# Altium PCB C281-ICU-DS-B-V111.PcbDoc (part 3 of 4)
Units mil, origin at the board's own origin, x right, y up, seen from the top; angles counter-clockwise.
Board outline 9370.03 x 5995.03 mil, 2 copper layers (Top Layer, Bottom Layer); 468 components, 321 nets, 1241 pads, 808 vias.
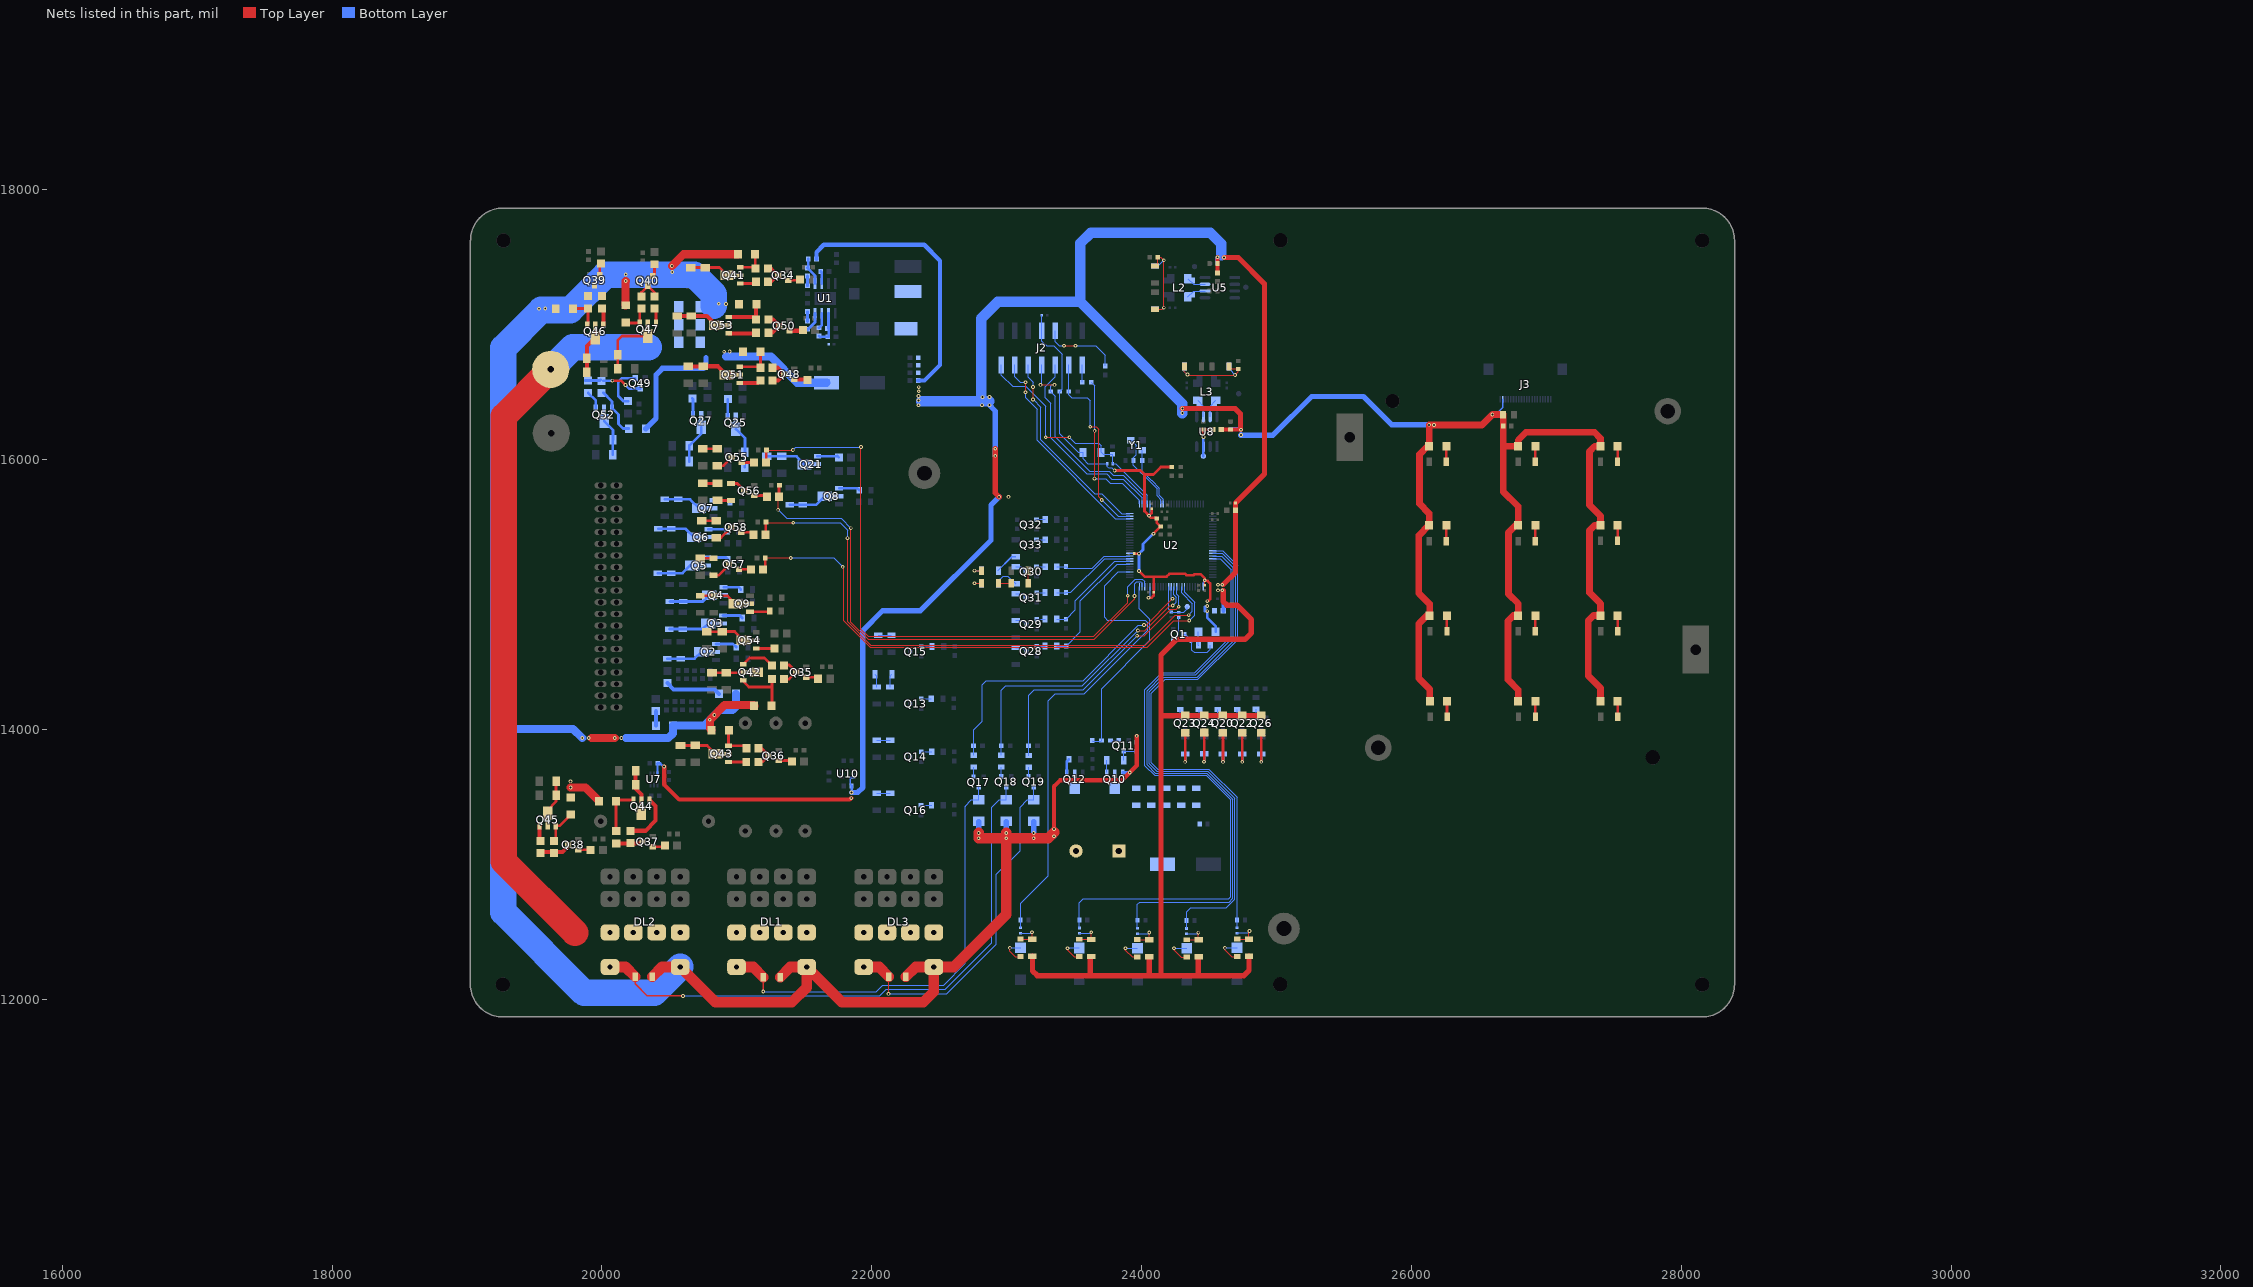
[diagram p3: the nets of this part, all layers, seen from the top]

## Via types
v1: diameter 27.56, hole 13.78, Top Layer to Bottom Layer, tented both sides, 808 vias

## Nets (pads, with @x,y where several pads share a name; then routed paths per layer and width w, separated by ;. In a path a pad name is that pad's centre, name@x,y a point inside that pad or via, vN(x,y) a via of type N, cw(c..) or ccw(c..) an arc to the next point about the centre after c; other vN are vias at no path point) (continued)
NetC35_1: C35.1 FB5.1 TP18.1 U8.3 | length 262.3
  Top Layer w7.87: v1@24457.48,16169.87 v1(24457.95,16169.4)
  Top Layer w19.68: v1@24457.48,16169.87 C35.1@24457.48,16223.93 FB5.1@24521.48,16223.93
  Bottom Layer w19.68: TP18.1@24457.48,16027 24457.48,16037.93 24457.95,16037.46 U8.3@24457.95,16097.48 v1(24457.95,16169.4)
NetC36_1: C36.1 R43.1 R44.1 R126.1 R128.1 | length 701.2
  Top Layer w7.87: R126.1@24100.09,17114.69 24152.11,17114.69 v1(24165.09,17127.68) v1(24165.09,17478.68) 24143.09,17500.68 C36.1@24119.09,17500.68 24119.09,17455.66 R44.1@24100.09,17436.66
  Bottom Layer w7.87: R128.1@24100.09,17114.69 24152.11,17114.69 v1(24165.09,17127.68) ; R43.1@24100.09,17436.66 24123.08,17436.66 v1(24165.09,17478.68)
NetC38_1: C38.1 R125.1 R127.1 R129.1 R130.1 | length 699.7
  Top Layer w7.87: R129.1@24317.6,16689.76 24317.6,16653.81 v1(24339.48,16631.93) 24343.48,16627.93 v1(24693.48,16627.93) 24716.48,16650.93 C38.1@24716.48,16672.93 24665.14,16672.93 R127.1@24648.31,16689.76
  Bottom Layer w7.87: R130.1@24317.6,16689.76 24317.6,16653.81 v1(24339.48,16631.93) ; R125.1@24648.31,16689.76 24648.31,16673.1 v1(24693.48,16627.93)
NetC52_2: C52.2 U1.6 | length 93
  Bottom Layer w20: C52.2@21622.08,17396.11 21629.39,17388.79 U1.6@21629.39,17306.11
NetC53_1: C53.1 C54.1 R135.2 R136.2 R137.2 R138.2 R140.2 SP1.1
NetD4_2: D4.2 Q41.E R211.1 | length 221.9
  Top Layer w20: Q41.E@21024.33,17426.53 21129.75,17426.53 R211.1@21135.13,17421.16 ; D4.2@21135.13,17524 R211.1@21135.13,17421.16 ; R211.1@21139.36,17416.92 R211.1@21135.13,17421.16
NetD6_1: D6.1 SW1.2 | length 211.4
  Top Layer w7.87: v1(23450,12379) 23450,12367.04 23500.21,12316.83 D6.1@23538.83,12316.83
  Bottom Layer w7.87: v1(23450,12379) 23452.3,12381.3 SW1.2@23538.83,12381.3
NetD6_2: D6.2 R45.1 R46.1 | length 239.6
  Top Layer w7.87: D6.2@23538.83,12445.77 23625.93,12445.77 23626.93,12444.77 v1@23626.93,12490.11 ; v1(23626.93,12498) v1@23626.93,12490.11 ; v1@23627.43,12489.62 v1@23626.93,12490.11
  Bottom Layer w7.87: R46.1@23538.83,12489.57 23627.38,12489.57 23626.93,12490.02 v1(23626.93,12498)
NetD7_2: D7.2 Q42.E R212.1 | length 442.5
  Top Layer w20: Q42.E@21047.84,14365 21047.84,14357.16 21089,14316 21252.86,14316 21259.86,14309 ; D7.2@21255.68,14175 21259.86,14179.18 21259.86,14309 ; R212.1@21259.86,14376 21259.86,14309
NetD8_1: D8.1 SW5.2 | length 214.7
  Top Layer w7.87: v1(24617,12382) 24617,12369.58 24668.75,12317.83 D8.1@24707.37,12317.83
  Bottom Layer w7.87: v1(24617,12382) 24617.3,12382.3 SW5.2@24707.37,12382.3
NetD8_2: D8.2 R55.1 R58.1 | length 254.5
  Top Layer w7.87: D8.2@24707.37,12446.77 24794.48,12446.77 R55.1@24795,12446.25 ; R55.1@24795.95,12445.29 24795.95,12503.21 v1(24799,12506.25)
  Bottom Layer w7.87: R58.1@24707.37,12490.57 24712.29,12495.49 24799,12495.49 v1(24799,12506.25)
NetD9_1: D9.1 SW2.2 | length 198.4
  Top Layer w7.87: v1(23023.55,12382.3) 23023.55,12357.95 23063.67,12317.83 D9.1@23102.29,12317.83
  Bottom Layer w7.87: v1(23023.55,12382.3) SW2.2@23102.29,12382.3
NetD9_2: D9.2 R119.1 R120.1 | length 243.1
  Top Layer w7.87: D9.2@23102.29,12446.77 R119.1@23189.4,12446.77 ; v1(23187.63,12498) v1@23187.63,12493.88 ; R119.1@23190.87,12445.29 R119.1@23189.4,12446.77 ; v1@23190.89,12490.62 v1@23187.63,12493.88 ; v1@23187.63,12493.88 23187.63,12448.54 R119.1@23189.4,12446.77
  Bottom Layer w7.87: R120.1@23102.29,12490.57 23190.84,12490.57 23187.63,12493.78 v1(23187.63,12498)
NetD10_2: D10.2 Q43.E R213.1 | length 257.6
  Top Layer w20: D10.2@20939.93,13996 20937.42,13993.5 Q43.E@20937.42,13879.67 21052.17,13879.67 R213.1@21070.17,13861.67
NetD11_2: D11.2 Q44.E R214.1 | length 356.4
  Top Layer w20: R214.1@20106,13247 20104.06,13248.94 D11.2@20104.06,13470 20112.39,13478.33 Q44.E@20233.25,13478.33
NetD12_1: D12.1 SW3.2 | length 213
  Top Layer w7.87: v1(23880,12379) 23880,12365.4 23930.56,12314.83 D12.1@23969.18,12314.83
  Bottom Layer w7.87: v1(23880,12379) 23880.3,12379.3 SW3.2@23969.18,12379.3
NetD12_2: D12.2 R65.1 R66.1 | length 241.1
  Top Layer w7.87: D12.2@23969.18,12443.77 R65.1@24056.29,12443.77 ; v1(24056.29,12495.98) v1@24056.29,12489.11 ; R65.1@24057.76,12442.29 R65.1@24056.29,12443.77 ; v1@24057.78,12487.62 v1@24056.29,12489.11 ; R65.1@24056.29,12443.77 v1@24056.29,12489.11
  Bottom Layer w7.87: R66.1@23969.18,12487.57 24057.73,12487.57 24056.29,12489.01 v1(24056.29,12495.98)
NetD13_2: D13.2 Q45.E R215.1 | length 263.4
  Top Layer w20: R215.1@19644.01,13175.19 19657.76,13188.94 Q45.E@19657.76,13283.86 19657.76,13287.86 19687.43,13287.86 D13.2@19769,13369.44
NetD14_1: D14.1 SW4.2 | length 220.1
  Top Layer w7.87: v1(24240,12379) 24240,12368.57 24294.74,12313.83 D14.1@24333.35,12313.83
  Bottom Layer w7.87: v1(24240,12379) 24240.7,12378.3 SW4.2@24333.35,12378.3
NetD14_2: D14.2 R71.1 R72.1 | length 239
  Top Layer w7.87: D14.2@24333.35,12442.77 24420.46,12442.77 v1@24420.46,12488.11 ; v1(24420.46,12495) v1@24420.46,12488.11 ; v1@24421.95,12486.62 v1@24420.46,12488.11
  Bottom Layer w7.87: R72.1@24333.35,12486.57 24421.91,12486.57 24420.46,12488.01 v1(24420.46,12495)
NetD15_2: D15.2 Q46.E R216.1 | length 237.9
  Top Layer w20: D15.2@19784.68,17121 19895.5,17121 R216.1@19896.99,17122.5 19896.99,17007.07 Q46.E@19890.25,17000.33
NetD19_2: D19.2 Q47.E R217.1 | length 218.5
  Top Layer w20: D19.2@20174.55,17018 20178.77,17013.78 Q47.E@20280.25,17013.78 20280.25,17108.25 R217.1@20292,17120
NetD20_2: D20.2 Q51.E R233.1 | length 278.5
  Top Layer w20: Q51.E@21020.53,16689.25 21168.06,16689.25 R233.1@21175.3,16682.01 21175.3,16800.26 D20.2@21173.56,16802
NetD21_2: D21.2 Q52.E R234.1 | length 367.9
  Bottom Layer w20: R234.1@20010,16496.59 20074.75,16431.84 Q52.E@20074.75,16383.33 20122,16336.08 20122,16266 20157,16231 D21.2@20198.44,16231
NetD22_2: D22.2 Q53.E R235.1 | length 322
  Top Layer w30: Q53.E@20939.93,17057.35 21125.98,17057.35 R235.1@21142.73,17040.6 21142.73,17150 D22.2@21144.74,17152
NetD24_1: D24.1 R240.2 | length 106
  Bottom Layer w30: D24.1@20399,14030 R240.2@20399,14136.04
NetD25_1: D25.1 R244.2 | length 414.7
  Bottom Layer w30: R244.2@20484.5,14344.61 20531.11,14298 20832.56,14298 D25.1@20866,14264.56
NetJ2_1: J2.1 R10.2 | length 128.4
  Bottom Layer w7.87: R10.2@23560,16575 J2.1@23560,16703.43
NetJ2_6: J2.6 R11.1 | length 573
  Top Layer w7.87: v1(23425,16845) v1(23510,16845)
  Bottom Layer w7.87: J2.6@23360,16956.57 23360,16875 23390,16845 v1(23425,16845) ; v1(23510,16845) 23660,16845 23730,16775 R11.1@23730,16695
NetL2_2: L2.2 U5.6 | length 144.4
  Bottom Layer w7.87: L2.2@24343.09,17208.75 24385.02,17250.68 U5.6@24470.09,17250.68
NetL2_3: L2.3 U5.7 | length 144.4
  Bottom Layer w7.87: L2.3@24343.08,17342.6 24385.01,17300.68 U5.7@24470.09,17300.68
NetL3_2: L3.2 U8.6 | length 139.6
  Bottom Layer w7.87: L3.2@24416.03,16439.76 24457.95,16397.84 U8.6@24457.95,16317.48
NetL3_3: L3.3 U8.7 | length 139.7
  Bottom Layer w7.87: U8.7@24507.95,16317.48 24507.95,16397.84 L3.3@24549.88,16439.77
NetLED1_2: LED1.2 R22.2 | length 100.1
  Bottom Layer w7.87: LED1.2@24421.44,14725 24421.44,14625.26 R22.2@24421.69,14625
NetLED4_2: LED4.2 R76.1 | length 274.9
  Top Layer w19.68: v1(24322.73,13760.56) LED4.2@24322.73,13976.47
  Bottom Layer w19.68: v1(24322.73,13760.56) R76.1@24322.73,13819.56
NetLED5_2: LED5.2 R77.1 | length 274.9
  Top Layer w19.68: v1(24463.2,13761.27) LED5.2@24463.2,13977.17
  Bottom Layer w19.68: v1(24463.2,13761.27) R77.1@24463.2,13820.26
NetLED6_2: LED6.2 R78.1 | length 274.9
  Top Layer w19.68: v1(24603.04,13760.56) LED6.2@24603.05,13976.47
  Bottom Layer w19.68: v1(24603.04,13760.56) R78.1@24603.04,13819.56
NetLED7_2: LED7.2 R82.1 | length 115.2
  Top Layer w20: R82.1@26257.99,15985 26258.56,15985.57 LED7.2@26258.56,16100
NetLED8_2: LED8.2 R83.1 | length 115.2
  Top Layer w20: R83.1@26917.99,15985 26918.56,15985.57 LED8.2@26918.56,16100
NetLED9_2: LED9.2 R79.1 | length 274.9
  Top Layer w19.68: v1(24745.84,13760.56) LED9.2@24745.84,13976.47
  Bottom Layer w19.68: v1(24745.84,13760.56) R79.1@24745.84,13819.56
NetLED10_2: LED10.2 R85.1 | length 115.2
  Top Layer w20: R85.1@27527.99,15985 27528.56,15985.57 LED10.2@27528.56,16100
NetLED11_2: LED11.2 R80.1 | length 274.9
  Top Layer w19.68: v1(24886.43,13760.56) LED11.2@24886.43,13976.47
  Bottom Layer w19.68: v1(24886.43,13760.56) R80.1@24886.43,13819.56
NetLED12_2: LED12.2 R87.1 | length 120.2
  Top Layer w7.87: LED12.2@26257.99,15514.43 LED12.2@26258.56,15515
  Top Layer w19.68: R87.1@26257.99,15395 LED12.2@26257.99,15514.43
NetLED14_2: LED14.2 R89.1 | length 120.2
  Top Layer w20: R89.1@26917.99,15395 26918.56,15395.57 LED14.2@26918.56,15515
NetLED16_2: LED16.2 R91.1 | length 115.2
  Top Layer w20: R91.1@27527.99,15400 27528.56,15400.57 LED16.2@27528.56,15515
NetLED18_2: LED18.2 R93.1 | length 115.4
  Top Layer w20: LED18.2@26262.13,14845 26262.13,14730.87 R93.1@26262.99,14730
NetLED20_2: LED20.2 R95.1 | length 115.2
  Top Layer w20: R95.1@26917.99,14730 26918.56,14730.57 LED20.2@26918.56,14845
NetLED22_2: LED22.2 R97.1 | length 115.6
  Top Layer w20: LED22.2@27528.56,14845 27530,14843.56 R97.1@27530,14730
NetLED23_2: LED23.2 R98.1 | length 115.6
  Top Layer w20: LED23.2@26263.56,14210 26263.56,14096.44 R98.1@26265,14095
NetLED24_2: LED24.2 R99.1 | length 115.6
  Top Layer w20: LED24.2@26918.56,14210 26918.56,14096.44 R99.1@26920,14095
NetLED25_2: LED25.2 R100.1 | length 115.6
  Top Layer w20: LED25.2@27528.56,14210 27528.56,14096.44 R100.1@27530,14095
NetQ1_B: Q1.B R24.1 | length 177.4
  Bottom Layer w7.87: Q1.B@24234.63,14670.6 24275,14710.97 R24.1@24275,14831.31
NetQ1_C: Q1.C R22.1 TP13.1 | length 331.2
  Bottom Layer w7.87: Q1.C@24313.37,14708 24323,14708 24373,14658 24373,14588.91 24389.54,14572.36 24486.09,14572.36 24508.31,14594.58 R22.1@24508.31,14625
NetQ2_B: Q2.B R103.1 | length 161.6
  Bottom Layer w20: Q2.B@20844.53,14634.54 20971.57,14634.54 R103.1@20996.01,14610.11
NetQ2_C: Q2.C R26.1 R27.1 | length 271.9
  Bottom Layer w20: R27.1@20485.25,14525.42 R26.1@20583.67,14525.42 20686.29,14525.42 Q2.C@20736.4,14575.53
NetQ3_B: Q3.B R106.1 | length 150.9
  Bottom Layer w20: Q3.B@20896.45,14845.44 21022.3,14845.44 R106.1@21040.01,14827.73
NetQ3_C: Q3.C R28.1 R29.1 | length 305.4
  Bottom Layer w20: R28.1@20500.1,14744.82 R29.1@20598.53,14744.82 20746.71,14744.82 Q3.C@20788.31,14786.43
NetQ4_B: Q4.B R107.1 | length 133.5
  Bottom Layer w20: Q4.B@20902.53,15055.3 21011.98,15055.3 R107.1@21029.01,15038.28
NetQ4_C: Q4.C R30.1 R31.1 | length 309.9
  Bottom Layer w20: R31.1@20503.82,14949.67 R30.1@20602.25,14949.67 20747.78,14949.67 Q4.C@20794.4,14996.28
NetQ5_B: Q5.B R108.1 | length 160.5
  Bottom Layer w20: Q5.B@20778.2,15275.02 20917.62,15275.02 R108.1@20932.51,15260.12
NetQ5_C: Q5.C R32.1 R74.1 | length 278.6
  Bottom Layer w20: R32.1@20415.1,15159.01 R74.1@20513.53,15159.01 20596.7,15159.01 20653.7,15216 Q5.C@20670.06,15216
NetQ6_B: Q6.B R109.1 | length 144
  Bottom Layer w20: Q6.B@20790.04,15485.65 20911.81,15485.65 R109.1@20927.51,15469.94
NetQ6_C: Q6.C R88.1 R90.1 | length 290.9
  Bottom Layer w20: R88.1@20416.72,15488.65 R90.1@20515.15,15488.65 20619.88,15488.65 Q6.C@20681.9,15426.63
NetQ7_B: Q7.B R110.1 | length 129
  Bottom Layer w20: Q7.B@20826.89,15700.01 20933.66,15700.01 R110.1@20949.36,15684.31
NetQ7_C: Q7.C R92.1 R94.1 | length 280
  Bottom Layer w20: R92.1@20465.9,15706.5 R94.1@20564.32,15706.5 20653.25,15706.5 Q7.C@20718.75,15641
NetQ8_B: Q8.B R111.1 | length 154.2
  Bottom Layer w20: Q8.B@21758.57,15787.91 21893.33,15787.91 R111.1@21907.04,15774.2
NetQ8_C: Q8.C R96.1 R101.1 | length 284.4
  Bottom Layer w20: R101.1@21391.43,15667.58 R96.1@21489.85,15667.58 21589.11,15667.58 Q8.C@21650.43,15728.89
NetQ9_B: Q9.B R123.1 | length 147.8
  Top Layer w20: Q9.B@21098,14873 21236.95,14873 R123.1@21243.19,14879.23
NetQ9_C: Q9.C R121.1 R122.1 | length 287.4
  Top Layer w20: R121.1@20726.86,14990.98 R122.1@20827.2,14990.98 20930.89,14990.98 Q9.C@20989.86,14932.02
NetQ10_2: Q10.2 R135.1 R136.1 R137.1 R138.1 R140.1
NetQ10_3: Q10.3 R134.2 | length 88.6
  Bottom Layer w7.87: Q10.3@23741.95,13682.33 R134.2@23741.95,13770.91
NetQ11_B: Q11.B R139.2 | length 60.5
  Bottom Layer w7.87: R139.2@23770.13,13918.91 23770.49,13918.55 Q11.B@23830.53,13918.55
NetQ11_C: Q11.C R133.2 R134.1 | length 165
  Bottom Layer w7.87: R134.1@23867.93,13770.91 Q11.C@23867.93,13839.81 R133.2@23963.99,13839.81
NetQ12_2: Q12.2 SP1.2
NetQ12_3: Q12.3 R142.2 | length 104.2
  Bottom Layer w19.68: Q12.3@23445.37,13682.33 23445.37,13764.23 R142.2@23461.12,13779.98
NetQ13_B: Q13.B R59.2 | length 75.2
  Bottom Layer w7.87: Q13.B@22366.14,14228.74 R59.2@22441.35,14228.74
NetQ14_B: Q14.B R62.2 | length 77.2
  Bottom Layer w7.87: Q14.B@22366.14,13835.04 R62.2@22443.32,13835.04
NetQ15_B: Q15.B R73.2 | length 79.9
  Bottom Layer w7.87: Q15.B@22366.14,14615.75 R73.2@22446,14615.75
NetQ16_B: Q16.B R148.2 | length 79.3
  Bottom Layer w7.87: Q16.B@22363.78,13438.98 R148.2@22443.09,13438.98
NetQ17_B: Q17.B R150.2 | length 71.6
  Bottom Layer w7.87: Q17.B@22754.67,13650.58 R150.2@22754.67,13722.22
NetQ18_B: Q18.B R151.2 | length 71.1
  Bottom Layer w7.87: R151.2@22959.08,13722.22 22959.6,13721.7 Q18.B@22959.6,13651.37
NetQ19_B: Q19.B R152.2 | length 69.9
  Bottom Layer w7.87: Q19.B@23162.35,13651.37 R152.2@23162.35,13721.24
NetQ20_B: Q20.B R156.2 | length 62.1
  Bottom Layer w7.87: R156.2@24565.45,14148.62 24565.45,14086.8 Q20.B@24565.65,14086.6
NetQ21_B: Q21.B R35.1 | length 169.6
  Bottom Layer w16: R35.1@21742.14,16031.11 21747.14,16026.11 R35.1@21756.39,16016.86
  Bottom Layer w20: Q21.B@21597.71,16026.11 R35.1@21747.14,16026.11
NetQ21_C: Q21.C R7.1 R8.1 | length 304.6
  Bottom Layer w20: R7.1@21222.02,16025.91 21333.02,16025.91 R8.1@21334.02,16024.91 21441.34,16024.91 Q21.C@21501.39,15964.86
NetQ22_B: Q22.B R159.2 | length 62
  Bottom Layer w7.87: Q22.B@24708.44,14086.6 R159.2@24708.44,14148.62
NetQ23_B: Q23.B R160.2 | length 62
  Bottom Layer w7.87: Q23.B@24285.33,14086.6 R160.2@24285.33,14148.62
NetQ24_B: Q24.B R164.2 | length 62
  Bottom Layer w7.87: Q24.B@24425.8,14086.6 R164.2@24425.8,14148.62
NetQ25_B: Q25.B R36.1 | length 126.1
  Bottom Layer w20: Q25.B@20932,16323.33 20932,16447.94 R36.1@20933.05,16448.99
NetQ25_C: Q25.C R13.1 R14.1 | length 311.4
  Bottom Layer w16: R13.1@21058.49,16054.18 R13.1@21059.49,16055.18
  Bottom Layer w20: Q25.C@20993.25,16227 21059.49,16160.76 R13.1@21059.49,16055.18 ; R14.1@21058.49,15943.45 R13.1@21058.49,16054.18
NetQ26_B: Q26.B R166.2 | length 64.1
  Bottom Layer w7.87: R166.2@24848.05,14150.68 24848.05,14088.02 Q26.B@24849.03,14087.04
NetQ27_B: Q27.B R37.1 | length 120.5
  Bottom Layer w20: R37.1@20669.97,16455.08 20675.04,16450.01 Q27.B@20675.04,16336.65
NetQ27_C: Q27.C R16.1 R17.1 | length 289.9
  Bottom Layer w20: R17.1@20647.98,15987.01 R16.1@20647.98,16105.01 20736.29,16193.32 Q27.C@20736.29,16240.33
NetQ28_B: Q28.B R172.2 | length 61.3
  Bottom Layer w7.87: Q28.B@23223,14618.31 23223.69,14619 R172.2@23284,14619
NetQ29_B: Q29.B R173.2 | length 61.2
  Bottom Layer w7.87: Q29.B@23223,14818.5 23283.5,14818.5 R173.2@23284,14819
NetQ30_B: Q30.B R176.2 | length 65.3
  Bottom Layer w7.87: Q30.B@23220,15208.66 23284.34,15208.66 R176.2@23285,15208
NetQ31_B: Q31.B R177.2 | length 62
  Bottom Layer w7.87: Q31.B@23222,15016.1 23222.1,15016 R177.2@23284,15016
NetQ32_B: Q32.B R188.2 | length 64.3
  Bottom Layer w7.87: Q32.B@23221.06,15557.19 R188.2@23285.39,15557.19
NetQ33_B: Q33.B R189.2 | length 65
  Bottom Layer w7.87: Q33.B@23220,15407 R189.2@23285,15407
NetQ34_B: Q34.B R158.1 | length 90.2
  Top Layer w20: Q34.B@21381.1,17330.42 21463.42,17330.42 R158.1@21469,17336
NetQ34_C: Q34.C R198.2 R211.2 | length 194.2
  Top Layer w20: R211.2@21229.37,17416.92 21257.85,17416.92 Q34.C@21306.85,17367.92 21258.68,17319.75 R198.2@21230.37,17319.75
NetQ35_B: Q35.B R161.1 | length 93.1
  Top Layer w20: Q35.B@21513.9,14389.01 21590.04,14389.01 R161.1@21602.05,14377
NetQ35_C: Q35.C R205.2 R212.2 | length 200.2
  Top Layer w20: R205.2@21360.9,14478.01 21388.15,14478.01 Q35.C@21439.65,14426.51 21387.15,14374.01 R212.2@21361.26,14374.01
NetQ36_B: Q36.B R165.1 | length 100.5
  Top Layer w20: Q36.B@21310.55,13770.17 21399.52,13770.17 R165.1@21407.69,13762
NetQ36_C: Q36.C R206.2 R213.2 | length 194.8
  Top Layer w20: R206.2@21159.42,13760.67 21189.3,13760.67 Q36.C@21236.3,13807.67 21182.3,13861.67 R213.2@21160.17,13861.67
NetQ37_B: Q37.B R168.1 | length 92.4
  Top Layer w20: Q37.B@20377.12,13132.5 20457.5,13132.5 R168.1@20466,13141
NetQ37_C: Q37.C R207.2 R214.2 | length 202.3
  Top Layer w30: R214.2@20106,13157 20289.87,13157 Q37.C@20302.87,13170
NetQ38_B: Q38.B R170.1 | length 80.5
  Top Layer w20: Q38.B@19836.12,13109.5 19914.5,13109.5 R170.1@19916,13108
NetQ38_C: Q38.C R208.2 R215.2 | length 247.8
  Top Layer w30: R208.2@19545.01,13085.19 R208.2@19551.01,13091.19 ; R208.2@19545.01,13091.19 R208.2@19551.01,13091.19 ; R208.2@19554.82,13095 R208.2@19551.01,13091.19 ; Q38.C@19749.72,13146 19749.72,13134.84 19706.06,13091.19 R208.2@19551.01,13091.19
NetQ39_B: Q39.B R171.1 | length 91.7
  Top Layer w20: Q39.B@19982.49,17367.05 19982.49,17445.27 R171.1@19992,17454.78
NetQ39_C: Q39.C R209.2 R216.2
NetQ40_B: Q40.B R196.1 | length 91.6
  Top Layer w20: Q40.B@20377.5,17362.12 20389,17373.62 R196.1@20389,17449
NetQ40_C: Q40.C R210.2 R217.2 | length 195.9
  Top Layer w20: R217.2@20292,17210 20292,17239.87 Q40.C@20340,17287.87 20389,17238.87 R210.2@20389,17210
NetQ41_B: Q41.B R198.1 | length 121.5
  Top Layer w20: Q41.B@21024.33,17306.53 21127.14,17306.53 R198.1@21140.36,17319.76
NetQ41_C: Q41.C R41.1 R42.1 | length 293.2
  Top Layer w20: R42.1@20658.3,17424.51 R41.1@20765.23,17424.51 20871.27,17424.51 Q41.C@20928,17367.78
NetQ42_B: Q42.B R205.1 | length 254
  Top Layer w20: Q42.B@21047.84,14485 21093.84,14531 21205,14531 R205.1@21260,14476
NetQ42_C: Q42.C R53.1 R57.1 | length 339.5
  Top Layer w20: R57.1@20823.04,14429 R57.1@20815.79,14421.75 R53.1@20922.22,14421.75 21142.17,14421.75 Q42.C@21144.16,14423.75
NetQ43_B: Q43.B R206.1 | length 138.2
  Top Layer w20: Q43.B@20937.42,13759.67 21054.42,13759.67 21062.42,13767.67 R206.1@21069.42,13760.67
NetQ43_C: Q43.C R60.1 R61.1 | length 284.7
  Top Layer w20: R61.1@20582,13882.18 R60.1@20690,13882.18 ; R60.1@20690,13882.68 20779.33,13882.68 Q43.C@20841.1,13820.92
NetQ44_B: Q44.B R207.1 | length 388.6
  Top Layer w30: R207.1@20212,13248 20214.06,13250.06 20321.06,13250.06 20398,13327 20398,13433.58 Q44.B@20353.25,13478.33
NetQ44_C: Q44.C R63.1 R64.1 | length 243.8
  Top Layer w30: R64.1@20249.99,13693.93 R63.1@20249.99,13590.5 20249.99,13562.79 20293.25,13519.53 Q44.C@20293.25,13468.09
NetQ45_B: Q45.B R208.1 | length 115.7
  Top Layer w30: Q45.B@19537.76,13287.86 Q45.B@19537.76,13283.86 19537.76,13182.44 R208.1@19545.01,13175.19
NetQ45_C: Q45.C R68.1 R69.1 | length 237.8
  Top Layer w20: Q45.C@19599.01,13405.19 19660.02,13466.21 R68.1@19660.02,13514.29 R69.1@19660.02,13617.72
NetQ46_B: Q46.B R209.1 | length 111
  Top Layer w30: Q46.B@20010.25,17000.33 R209.1@20010.25,17111.35
NetQ46_C: Q46.C R81.1 R84.1 | length 279.7
  Top Layer w30: R84.1@19887.97,16649.62 R81.1@19887.97,16753.05 19887.97,16842.97 Q46.C@19949,16904
NetQ47_B: Q47.B R210.1 | length 110.9
  Top Layer w20: R210.1@20389,17120 20400.25,17108.75 Q47.B@20400.25,17013.78
NetQ47_C: Q47.C R131.1 R132.1 | length 447.2
  Top Layer w20: R132.1@20117.26,16673.69 R131.1@20117.26,16777.12 20117.26,16886.26 20148.45,16917.45 Q47.C@20339,16917.45
NetQ48_B: Q48.B R224.1 | length 99.8
  Top Layer w30: Q48.B@21424.62,16595.34 21519.66,16595.34 R224.1@21523,16592
NetQ48_C: Q48.C R229.2 R233.2 | length 210.2
  Top Layer w30: R229.2@21264.98,16586.01 21303.53,16586.01 Q48.C@21350.37,16632.84 21301.2,16682.01 R233.2@21265.31,16682.01
NetQ49_B: Q49.B R225.1 | length 331
  Bottom Layer w20: R225.1@20194,16433.85 20159.41,16433.85 20120.59,16472.67 20120.59,16577.72 20146,16603.12 Q49.B@20246.5,16603.12
NetQ49_C: Q49.C R230.2 R234.2 | length 413.1
  Top Layer w20: v1(20077.14,16586.59) 20141.95,16586.59 v1(20173.77,16554.78)
  Bottom Layer w20: R230.2@19876,16587.59 19983,16587.59 R234.2@19988.81,16593.41 ; R234.2@20010,16586.59 v1(20077.14,16586.59) ; v1(20173.77,16554.78) 20199.68,16528.87 Q49.C@20284,16528.87
NetQ50_B: Q50.B R226.1 | length 101.7
  Top Layer w30: Q50.B@21389.83,16956.35 21483,16956.35 R226.1@21489,16962.35
NetQ50_C: Q50.C R232.2 R235.2 | length 206.7
  Top Layer w30: R232.2@21232.73,16941.6 21263.32,16941.6 Q50.C@21315.57,16993.85 21268.83,17040.6 R235.2@21232.73,17040.6
NetQ51_B: Q51.B R229.1 | length 161.4
  Top Layer w30: Q51.B@21020.53,16569.25 21158.22,16569.25 R229.1@21174.98,16586.01
NetQ51_C: Q51.C R218.1 R219.1 | length 365.6
  Top Layer w30: R219.1@20640.5,16692.5 20805.5,16692.5 ; R218.1@20749.49,16692.99 20861.71,16692.99 Q51.C@20924.2,16630.5
NetQ52_B: Q52.B R230.1 | length 136.6
  Bottom Layer w20: R230.1@19898,16496.4 19954.75,16439.65 Q52.B@19954.75,16383.33
NetQ52_C: Q52.C R220.1 R221.1 | length 277.8
  Bottom Layer w16: R220.1@20080.01,16146.36 R220.1@20082,16148.35
  Bottom Layer w20: Q52.C@20016,16287 20082,16221 R220.1@20082,16148.35 ; R221.1@20080.01,16037.35 R220.1@20080.01,16146.36
NetQ53_B: Q53.B R232.1 | length 204.6
  Top Layer w30: Q53.B@20939.93,16937.35 21138.48,16937.35 R232.1@21142.73,16941.6
NetQ53_C: Q53.C R222.1 R223.1 | length 311.7
  Top Layer w30: R223.1@20559.57,17065.35 R222.1@20663,17065.35 20776.86,17065.35 Q53.C@20843.6,16998.6
NetQ54_B: Q54.B R238.1 | length 132.1
  Top Layer w20: Q54.B@21144.33,14600.75 21274.29,14600.75 R238.1@21275.78,14599.26
NetQ54_C: Q54.C R236.1 R237.1 | length 297.7
  Top Layer w20: R237.1@20777.43,14725.42 20890.89,14725.42 R236.1@20891.89,14726.42 20983.58,14726.42 Q54.C@21048,14662
NetQ55_B: Q55.B R250.2 | length 91.5
  Top Layer w20: Q55.B@21034.99,15979.6 R250.2@21126.49,15979.59
NetQ56_B: Q56.B R251.2 | length 97.8
  Top Layer w20: Q56.B@21128.49,15734.58 21213.57,15734.58 R251.2@21222.58,15725.57
NetQ57_B: Q57.B R254.2 | length 88.6
  Top Layer w20: Q57.B@21015.84,15189.1 21102.27,15189.1 R254.2@21103.78,15187.59
NetQ58_B: Q58.B R255.2 | length 97
  Top Layer w20: Q58.B@21033.79,15461.6 21105.82,15461.6 R255.2@21123.5,15443.92
NetR47_2: R47.2 R48.1 | length 98.4
  Bottom Layer w7.87: R47.2@22037.4,13921.26 R48.1@22135.83,13921.26
NetR49_2: R49.2 R50.1 | length 100.2
  Bottom Layer w7.87: R50.1@22023.62,14409.45 22037.4,14395.67 R49.2@22037.4,14314.96
NetR50_2: R50.2 R51.1 | length 100.2
  Bottom Layer w7.87: R51.1@22135.83,14314.96 22135.83,14395.67 R50.2@22149.61,14409.45
NetR52_2: R52.2 R56.1 | length 98.4
  Bottom Layer w7.87: R52.2@22047.24,14698.82 R56.1@22145.67,14698.82
NetR54_2: R54.2 R86.1 | length 98.4
  Bottom Layer w7.87: R54.2@22037.4,13527.56 R86.1@22135.83,13527.56
NetR183_2: R183.2 R184.1 | length 93.4
  Top Layer w7.87: R183.2@23158.98,15178 23159.98,15177 R184.1@23159.98,15085
NetR184_2: R184.2 R185.1 | length 95
  Top Layer w7.87: R185.1@22938.99,15085 R184.2@23034,15085
NetR185_2: R185.2 R186.1 | length 101.9
  Top Layer w7.87: v1(22762.06,15085) R185.2@22813.01,15085
  Bottom Layer w7.87: v1(22762.06,15085) R186.1@22813.01,15085
NetR186_2: R186.2 R187.1 | length 182.7
  Bottom Layer w7.87: R186.2@22938.99,15085 22938.99,15101.99 22975,15138 23008.58,15138 R187.1@23066,15080.58
NetR191_2: R191.2 R192.1 | length 101.9
  Top Layer w7.87: v1(22762.06,15178) R191.2@22813.01,15178
  Bottom Layer w7.87: v1(22762.06,15178) R192.1@22813.01,15178
NetR192_2: R192.2 R193.1 | length 171.4
  Bottom Layer w7.87: R192.2@22938.99,15178 22938.99,15180.99 22986,15228
  Bottom Layer w10: 22986,15228 23039.02,15281.02 R193.1@23066,15281.02
NetR245_2: R245.2 R246.1 | length 109.4
  Top Layer w20: R245.2@20746.99,16081.6 20747.98,16082.59 R246.1@20855.99,16082.59
NetR247_2: R247.2 R248.1 | length 111
  Top Layer w20: R247.2@20745.49,15824.58 R248.1@20856.49,15824.58
NetR248_2: R248.2 R249.1 | length 100.6
  Top Layer w20: R248.2@20856.5,15698.59 R249.1@20957.05,15698.59
NetR257_2: R257.2 R258.1 | length 99.4
  Top Layer w20: R257.2@20729.26,15270.6 20827.26,15270.6 R258.1@20828.26,15269.6
NetR263_2: R263.2 R264.1 | length 106.6
  Top Layer w20: R263.2@20739.79,15547.5 20844.26,15547.5 R264.1@20845.79,15549.03
NetR265_1: R265.1 R267.2 U1.5 | length 207.1
  Bottom Layer w20: R265.1@21529.08,17487.65 21529.08,17428 R267.2@21523.39,17422.32 21523.47,17422.32 21579.39,17366.4 U1.5@21579.39,17306.11
NetR266_2: R266.2 U1.3 | length 116.7
  Bottom Layer w20: R266.2@21608.39,16978.11 21629.39,16999.11 U1.3@21629.39,17086.11
NetR267_1: R267.1 R270.2 | length 72.9
  Bottom Layer w20: R270.2@21523.39,17288.74 R267.1@21523.39,17361.69
NetR268_1: R268.1 U1.4 | length 145.9
  Bottom Layer w20: R268.1@21523.39,16963.48 21523.47,16963.48 21579.39,17019.4 U1.4@21579.39,17086.11
NetR268_2: R268.2 R269.1 | length 72.4
  Bottom Layer w20: R268.2@21523.39,17024.11 R269.1@21523.39,17096.48
NTRST_MCU: J2.3 R12.1 U2.24 | length 1453.9
  Top Layer w7.87: v1(23619,16245) 23663,16245 23682,16226 23682,15725 v1(23704.5,15702.5)
  Bottom Layer w7.87: J2.3@23460,16703.43 R12.1@23460,16505 23460,16481 23482,16459 23597,16459 23619,16437 v1(23619,16245) ; v1(23704.5,15702.5) 23825.46,15581.54 U2.24@23912.91,15581.54
POWER: D1.1 D2.1 D3.1 DL1.9 DL1.10 DL1.11 DL1.12 DL2.9 DL2.10 DL2.11 DL2.12 DL3.9 DL3.10 DL3.11 DL3.12 J4.1 | length 5330.4
  Top Layer w196.85: J4.1@19620,16670 19272,16322 19272,13023 19800,12495
  Bottom Layer w196.85: J4.1@19620,16670 19783.11,16833.11 20345,16833.11
PR_LIGHT: R24.2 R25.2 TP14.1 U2.89 | length 338.1
  Bottom Layer w7.87: U2.89@24200.31,15057.91 24200.31,14891 R25.2@24220,14871.31 24274.37,14871.31 R24.2@24275,14870.68 24312,14870.68 24338.11,14896.8 TP14.1@24338.11,14911
RELAY_B+: D17.1 DL2.13 Q18.C R105.1 | length 4350.5
  Top Layer w11.81: R105.1@20246.62,12168.37 20246.62,12115.38 20336,12026 v1(20600.39,12026)
  Top Layer w50: DL2.13@20059.61,12231.37 DL2.13@20059.61,12240.43
  Top Layer w78.74: DL2.13@20059.61,12240.43 20174.55,12240.43 R105.1@20246.62,12168.37
  Bottom Layer w7.87: v1(20600.39,12026) 22058.36,12026 22106.7,12074.34 22544.23,12074.34 22890.18,12420.29 22890.18,13424.72 22943.98,13478.51 D17.1@22997,13478.51 Q18.C@22997,13572.63
RELAY_B+_MCU: R151.1 R154.2 U2.87 | length 2169.5
  Top Layer w7.87: v1(23972,14734) 24023.53,14734 24208.53,14919 v1(24231,14919)
  Bottom Layer w7.87: R151.1@22959.08,13808.83 R154.2@22959.08,13879.7 22959.08,14291.08 22992.39,14324.39 23560.19,14324.39 23969.81,14734 v1(23972,14734) ; v1(24231,14919) 24255,14943 24255,14982.52 24239.69,14997.83 U2.87@24239.69,15057.91
RELAY_B+~: D16.1 DL1.13 Q17.C R104.1 | length 3300
  Top Layer w11.81: v1(21195.77,12058) R104.1@21195.77,12165.37
  Top Layer w78.74: DL1.13@20997.31,12240.43 21120.71,12240.43 R104.1@21195.77,12165.37
  Bottom Layer w7.87: v1(21195.77,12058) 22032.88,12058 22081.18,12106.3 22532.68,12106.3 22693.21,12266.84 22693.21,13428.69 22691,13430.91 22738.61,13478.51 D16.1@22792.07,13478.51 Q17.C@22792.07,13571.84
RELAY_KL15: D18.1 DL3.13 Q19.C R75.1 | length 2602.4
  Top Layer w7.87: v1(22124.3,12041.1) 22124.3,12164.9 R75.1@22126.77,12167.37
  Top Layer w78.74: DL3.13@21940.08,12240.08 22054.06,12240.08 R75.1@22126.77,12167.37
  Bottom Layer w7.87: v1(22124.3,12041.1) 22557.1,12041.1 22923,12407 22923,12926 23099.31,13102.32 23099.31,13425.45 23152.38,13478.51 D18.1@23199.75,13478.51 Q19.C@23199.75,13572.63
RELAY_KL15_MCU: R152.1 R155.2 U2.86 | length 1984.7
  Top Layer w7.87: v1(23967,14695) 24018.3,14695 24215.29,14891.98 24257.14,14891.98 v1(24275.16,14910)
  Bottom Layer w7.87: R152.1@23162.35,13807.85 R155.2@23162.35,13879.7 23162.35,14253.22 23205.13,14296 23568,14296 v1(23967,14695) ; U2.86@24259.37,15057.91 24259.37,15003.79 24275.16,14988 v1(24275.16,14910)
RELAY_MCU_B+~: R150.1 R153.2 U2.88 | length 2316.7
  Top Layer w7.87: v1(24018,14775) 24033.86,14775 v1(24228.86,14970)
  Bottom Layer w7.87: R150.1@22754.67,13808.83 R153.2@22754.67,13879.7 22754.67,14000.4 22817.75,14063.48 22817.75,14331.75 22849,14363 23565.88,14363 23946.41,14743.53 23946.41,14744.6 23976.81,14775 v1(24018,14775) ; U2.88@24220,15057.91 24220,14978.86 v1(24228.86,14970)
RESET_MCU: C24.1 D5.1 J2.13 R19.1 U2.29 | length 1795.6
  Top Layer w7.87: v1(23289.92,16167.08) v1(23464.57,16167.08)
  Bottom Layer w7.87: J2.13@22960,16703.43 22960,16628 23043,16545 23140,16545 23289.92,16395.08 v1(23289.92,16167.08) ; v1(23464.57,16167.08) 23509.6,16122.05 23681.95,16122.05 23700,16104 D5.1@23700,16055 23715,16040 C24.1@23785,16040 R19.1@23785,15970 23810,15970 24042.83,15737.17 U2.29@24042.83,15672.09
SD_MODE_MCU: R139.1 R141.2 U2.100 | length 1394.3
  Bottom Layer w7.87: R141.2@23633.68,13918.55 23639.23,13913 23697.3,13913 R139.1@23703.21,13918.91 23703.21,14303.21 24062,14662 24062,14817 23983.78,14895.22 U2.100@23983.78,15057.91
SW_1: C40.1 R46.2 U2.68 | length 4818
  Bottom Layer w7.87: R46.2@23538.83,12528.94 C40.1@23538.83,12587.99 23538.83,12717.83 23566.06,12745.06 24645.2,12745.06 24660.24,12760.09 24660.24,13478.11 24477.83,13660.52 24096.06,13660.52 24024.83,13731.75 24024.83,14294.94 24150.38,14420.5 24394.5,14420.5 24664.75,14690.75 24664.75,15183.25 24581.43,15266.57 U2.68@24527.09,15266.57
SW_2: C49.1 R120.2 U2.3 | length 3579.6
  Bottom Layer w7.87: R120.2@23102.29,12529.94 C49.1@23102.29,12588.99 23102.29,12712.46 23308,12918.17 23308,14214.43 23360.38,14266.81 23575,14266.81 24046.25,14738.06 24046.25,14793.51 24027.76,14812 23746,14812 23726,14832 23726,15065.87 23828.28,15168.15 U2.3@23912.91,15168.15
SW_3: C45.1 R66.2 U2.67 | length 4437.8
  Bottom Layer w7.87: R66.2@23969.18,12526.94 C45.1@23969.18,12585.99 23969.18,12704.18 23987,12722 24648.87,12722 24675.98,12749.11 24675.98,13484.63 24484.35,13676.27 24102.58,13676.27 24040.58,13738.27 24040.58,14288.42 24156.91,14404.75 24401.02,14404.75 24680.5,14684.23 24680.5,15200.45 24594.68,15286.26 U2.67@24527.09,15286.26
SW_4: C47.1 R72.2 U2.66 | length 4089.2
  Bottom Layer w7.87: R72.2@24333.35,12525.94 C47.1@24333.35,12584.99 24333.35,12648.35 24364,12679 24628.14,12679 24691.73,12742.59 24691.73,13491.16 24490.87,13692.02 24112.83,13692.02 24056.32,13748.52 24056.32,14281.89 24163.43,14389 24411.24,14389 24696.24,14674 24696.24,15206.97 24597.27,15305.94 U2.66@24527.09,15305.94
SW_5: C42.1 R58.2 U2.65 | length 3806.1
  Bottom Layer w7.87: U2.65@24527.09,15325.63 24599.86,15325.63 24711.99,15213.49 24711.99,14667.48 24417.51,14373 24176,14373 24072.07,14269.07 24072.07,13755.05 24119.35,13707.76 24497.4,13707.76 24707.48,13497.68 24707.48,12689.48 24707.37,12689.37 R58.2@24707.37,12529.94
SYS_VCC_5: C19.1 C20.1 C27.1 C33.1 C34.1 C43.2 C44.2 C46.2 C48.2 C56.1 C62.1 C63.1 C66.1 FB3.2 FB4.2 FB5.2 FB7.1 J3.2 L4.2 LED4.1 LED5.1 LED6.1 LED7.1 LED8.1 LED9.1 LED10.1 LED11.1 LED12.1 LED14.1 LED16.1 LED18.1 LED20.1 LED22.1 LED23.1 LED24.1 LED25.1 R33.1 R34.1 R45.2 R55.2 R65.2 R71.2 R119.2 R265.2 U7.3 U10.3 | length 32664
  Top Layer w20: v1@24605,15075 v1@24606.35,15075
  Top Layer w31.5: v1(20461,13726) 20461,13592 20572,13481 21837,13481 v1(21848,13492) ; 24057.76,12181.24 24063,12176 ; 24144,12177 24145,12176 ; 24144,14103 24144.59,14103.59 ; FB4.2@24563.09,17384.61 C33.1@24563.09,17454.68 v1(24563.09,17500.68) ; FB5.2@24590.45,16223.93 24657.48,16223.93 C34.1@24658.48,16224.93 24733.03,16224.93 v1(24736,16221.96) ; v1@24604,15030 24610.84,15023.16 ; FB3.2@24695.96,15624.84 FB3.2@24696,15624.88 ; LED11.1@24877.18,14112.84 LED11.1@24886.43,14103.59
  Top Layer w39.37: v1(22915,16082) v1(22915,16029) 22915,15754.1 v1(22944.1,15725)
  Top Layer w40: R119.2@23190.87,12319.31 23190.87,12212.13 23227,12176 23618,12176 ; R45.2@23627.41,12318.31 23618,12308.9 23618,12176 ; 24057.76,12181.24 R65.2@24057.76,12316.31 ; 24144,12177 24144,14103 24144,14553 24260,14669 24765,14669 24813,14717 24813,14815.17 24706.17,14922 24632,14922 24604,14950 v1@24604,15030 ; 24144.59,14103.59 LED4.1@24322.73,14103.59 LED6.1@24603.05,14103.59 LED9.1@24745.84,14103.59 LED11.1@24886.43,14103.59 ; v1(24301.98,16380) 24693.04,16380 24733.03,16340.01 v1@24733.03,16224.93 ; R71.2@24421.94,12315.31 24420.46,12313.83 24420.46,12176 ; v1@24605,15075 24695.96,15165.96 FB3.2@24695.96,15624.84 ; v1(24610.55,17499) 24716.35,17499 24911.19,17304.16 24911.19,15894.19 C27.1@24696,15679 FB3.2@24696,15624.88 ; R55.2@24795.95,12319.31 24795.95,12213.95 24758,12176 24420.46,12176 ; 23618,12176 24063,12176 24145,12176 24420.46,12176
  Top Layer w50: LED23.1@26136.44,14210 26136.44,14298.56 26055,14380 26055,14785 26115,14845 LED18.1@26135,14845 26135,14930 26055,15010 26055,15438.56 LED12.1@26131.44,15515 26131.44,15602.8 26060,15674.24 26060,16040 26120,16100 LED7.1@26131.44,16100 v1(26131.44,16258.44) 26523.44,16258.44 v1(26600,16335) C63.1@26679.65,16335 26680.47,16334.17 C62.1@26680.47,16250 26680,16249.53 26680,16100 ; LED24.1@26791.44,14210 26791.44,14293.56 26715,14370 26715,14805 26755,14845 LED20.1@26791.44,14845 26791.44,14933.56 26720,15005 26720,15460 26775,15515 LED14.1@26791.44,15515 26791.44,15653.56 26680,15765 26680,16100 ; LED25.1@27401.44,14210 27401.44,14308.56 27310,14400 27310,14805 27350,14845 LED22.1@27401.44,14845 27401.44,14933.56 27320,15015 27320,15475 27360,15515 LED16.1@27401.44,15515 27401.44,15583.56 27320,15665 27320,16062 27358,16100 LED10.1@27401.44,16100 27401.44,16158.56 27356,16204 26850,16204 26791.44,16145.44 LED8.1@26791.44,16100 26680,16100
  Bottom Layer w11.81: v1(26600,16335) 26625.61,16335 26677.68,16387.06 J3.2@26677.68,16448.78
  Bottom Layer w14: U7.3@20410.59,13673.31 C66.1@20410.59,13747.2 ; C56.1@21850.39,13582.68 21840,13593.07 21840,13640.2 21845.47,13645.67 U10.3@21864.17,13645.67
  Bottom Layer w19.68: C66.1@20410.59,13747.2 C66.1@20413.39,13750 20431,13750 20455,13726 v1(20461,13726) ; v1(21850.39,13533.46) C56.1@21850.39,13582.68 ; R33.1@24553.25,17454.68 24553.25,17490.84 v1(24563.09,17500.68) ; R34.1@24658.48,16234.77 24723.19,16234.77 v1(24736,16221.96) ; v1@24734,16182 24734,16199.41
  Bottom Layer w30: FB7.1@24605.96,14880.87 v1@24605.96,15024.04
  Bottom Layer w31.5: R265.2@21589.71,17487.65 21589.71,17538.43 21644.39,17593.11 22388.39,17593.11 22506,17475.5 22506,16701.72 22391.39,16587.11 C48.2@22344.76,16587.11
  Bottom Layer w39.37: v1(21850.39,13533.46) 21895.46,13533.46 21934,13572 21934,14734 22081.18,14881.18 22361.18,14881.18 22883.23,15403.23 22883.23,15664.13 v1(22944.1,15725) ; 22872,16435 v1(22872,16405) 22915,16362 v1(22915,16082) v1(22915,16029) ; v1@24734,16182 24974,16182 25261,16469 25644,16469 25854.56,16258.44 v1(26131.44,16258.44)
  Bottom Layer w78.74: 22366.21,16435 22812,16435 ; 22872,16435 22812,16435 ; 24590.25,17516.86 24590.25,17600.57 24507.83,17683 23625.15,17683 23546,17603.85 23546,17170 ; 22812,16435 22812,17047 22935,17170 23546,17170 ; 23546,17170 24301.98,16414.02 ; 24301.98,16414.02 24302.04,16413.96 v1(24302.04,16346.04) 24301.98,16346.1 v1(24301.98,16380) 24301.98,16414.02
  other v1: 24566,15032 24598,15033 24566,15074 24598,15074 23013.72,15725 24736,16184 26167,16258 22346,16403.63 22817,16405 22346,16440.5 22820,16464 22872,16465 22347,16473 22348.58,16508 22348,16538
TCK_MCU: R10.1 U2.26 | length 1154.9
  Top Layer w7.87: v1(23650,15860) 23652,15862 v1(23652,16214.1)
  Bottom Layer w7.87: R10.1@23626.93,16575 23652,16549.93 v1(23652,16214.1) ; v1(23650,15860) 23735,15860 23768,15827 23858,15827 23983.78,15701.22 U2.26@23983.78,15672.09
TDI_MCU: J2.5 U2.27 | length 1494.8
  Bottom Layer w7.87: J2.5@23360,16703.43 23360,16615 23285,16540 23285,16460 23326.54,16418.46 23326.54,16163.43 23594.96,15895 23740,15895 23780,15855 23865,15855 24003.46,15716.54 U2.27@24003.46,15672.09
TDO_MCU: J2.7 R9.2 U2.28 | length 1582
  Top Layer w7.87: v1(23250,16555) v1(23355,16555)
  Bottom Layer w7.87: v1(23250,16555) 23260,16565 J2.7@23260,16703.43 ; v1(23355,16555) 23335,16555 23326.54,16546.54 R9.2@23326.54,16505 23360,16471.54 23360,16169 23614,15915 23760,15915 23789,15886 23864,15886 24023.15,15726.85 U2.28@24023.15,15672.09
TEM_RES1: Q55.C R246.2 | length 129.8
  Top Layer w20: R246.2@20855.99,15956.61 20900.25,15956.61 Q55.C@20960.74,16017.1
TEM_RES1_MCU: R250.1 R256.2 U2.98 | length 4571.4
  Top Layer w7.87: R256.2@21218.81,16071.59 v1@21414.78,16071.59 ; v1(21920,16094.18) 21920,14743.97 21973.97,14690 23646.97,14690 23897,14940.03 v1(23897,14992.37)
  Top Layer w20: R250.1@21216.5,15979.59 21218.81,15981.91 R256.2@21218.81,16071.59
  Bottom Layer w7.87: v1(21414.78,16072.99) 21435.98,16094.18 v1(21920,16094.18) ; v1(23897,14992.37) 23897,15059 23953,15115 24006,15115 24023.15,15097.85 U2.98@24023.15,15057.91
TEM_RES2: Q56.C R249.2 | length 144.6
  Top Layer w20: R249.2@20982.75,15824.57 R249.2@20957.05,15824.57 20958.05,15823.57 21002.75,15823.57 Q56.C@21054.24,15772.08
TEM_RES2_MCU: R251.1 R259.2 U2.99 | length 3969.8
  Top Layer w7.87: v1(21306,15628.53) 21306,15718.99 R251.1@21312.58,15725.57 ; v1(21845,15493) 21845.59,15492.41 21845.59,14796.11 21972.32,14669.38 23648.62,14669.38 23948,14968.76 v1(23948,14990)
  Top Layer w20: R251.1@21312.58,15725.57 21312.58,15808.62 R259.2@21315.53,15811.57
  Bottom Layer w7.87: v1(21306,15628.53) 21369.53,15565 21773,15565 v1(21845,15493) ; v1(23948,14990) 23948,15082 23963.28,15097.28 23998.72,15097.28 24003.46,15092.54 U2.99@24003.46,15057.91
TEM_RES3: Q57.C R258.2 | length 150.4
  Top Layer w20: R258.2@20828.26,15143.62 20863.26,15143.62 20941.59,15221.95 Q57.C@20941.59,15226.6
TEM_RES3_MCU: R254.1 R261.2 U2.83 | length 4108.6
  Top Layer w7.87: R261.2@21210.31,15272.07 v1(21399,15272.07) ; v1@21791,15198 21791,14806.16 21986.9,14610.25 24040.25,14610.25 24237.81,14807.81 v1(24353.18,14807.81)
  Top Layer w20: R254.1@21193.78,15187.59 21210.31,15204.12 R261.2@21210.31,15272.07
  Bottom Layer w7.87: v1(21399,15272.07) 21718.93,15272.07 v1(21785,15206) ; U2.83@24318.43,15057.91 24318.43,15018.3 24393.64,14943.09 24393.64,14848 24353.45,14807.81 v1(24353.18,14807.81)
TEM_RES4: Q58.C R264.2 | length 145.2
  Top Layer w20: R264.2@20845.79,15423.04 20883.48,15423.04 Q58.C@20959.54,15499.1
TEM_RES4_MCU: R255.1 R262.2 U2.84 | length 4348
  Top Layer w7.87: R262.2@21213.5,15536.28 21216.21,15533.56 v1(21417.37,15533.56) ; v1@21821.13,15419 21821.13,14798.3 21993.43,14626 24028,14626 24250,14848 v1(24349.31,14848)
  Top Layer w20: R255.1@21213.5,15443.92 R262.2@21213.5,15536.28
  Bottom Layer w7.87: v1(21417.37,15533.56) 21764.42,15533.56 21820,15477.99 v1(21820,15419) ; U2.84@24298.74,15057.91 24298.74,15012.65 24377,14934.39 24377,14875.69 v1(24349.31,14848)
TMS_MCU: J2.9 U2.25 | length 1479.2
  Top Layer w7.87: v1(23195,16446.85) v1(23195,16540)
  Bottom Layer w7.87: J2.9@23160,16703.43 23160,16610 23195,16575 v1(23195,16540) ; v1(23195,16446.85) 23253,16388.85 23253,16150 23654.2,15748.8 23704.2,15748.8 23851.78,15601.22 U2.25@23912.91,15601.22
TRDY_MCU: J2.11 U2.23 | length 1580.8
  Top Layer w7.87: v1(23140,16500) v1(23140,16575)
  Bottom Layer w7.87: J2.11@23060,16703.43 23060,16615 23100,16575 v1(23140,16575) ; v1(23140,16500) 23140,16458 23225,16373 23225,16143 23806.15,15561.85 U2.23@23912.91,15561.85
VCC5V_SYS: C11.1 C21.1 C22.1 C23.1 C64.1 D5.2 FB7.2 J2.8 LED1.1 R9.1 R15.1 R18.2 R19.2 R21.2 U2.10 U2.30 U2.76 U2.96 | length 4406.6
  Top Layer w7.87: v1@24468.46,15102.56 v1(24468.46,15106.64) 24468.46,15106.72 24468.94,15107.2 24468.94,15102.56 C23.1@24468.94,15070
  Top Layer w19.68: v1(23800,15920) 23992,15920 24021,15891 ; C21.1@23945,15305 23946,15304 v1(23981,15304) ; v1(23981,15175) 24023,15133 24088.69,15133 ; v1(24051,14977) 24072.2,14977 24088.69,14993.48 C64.1@24088.69,15017 24088.69,15133 ; C22.1@24075,15635.63 24075,15605 v1(24055,15585) ; v1(24087.79,15452) R18.2@24141.54,15505.75 24111.54,15535.75 R15.1@24111.54,15565 ; R15.1@24111.54,15570 24070,15570 v1(24055,15585) ; R21.2@24223.9,15946.57 24142.57,15946.57 24087,15891 24021,15891 ; v1@24468.46,15102.56 24468.94,15102.56 24488.44,15102.56 24508.35,15082.65 24508.35,14968.02 v1@24495.59,14955.26 ; v1@24468.46,15106.72 24468.46,15121.55 24437.91,15152.09 24393.5,15152.09 24384.96,15143.54 24334.07,15143.54 24323.61,15154 24206.54,15154 24185.54,15133 24088.69,15133 ; 24021,15891 24021,15619 v1(24055,15585)
  Bottom Layer w7.87: C11.1@23260.31,17070 23260,17069.69 J2.8@23260,16956.57 23260,16880 23295,16845 23347,16845 23410,16782 23410,16521.54 R9.1@23393.46,16505 23393.46,16191.54 23530,16055 D5.2@23566.14,16055 23566.14,16006.28 23602.42,15970 R19.2@23745.63,15970 23745.63,15949.37 23755,15940 23780,15940 v1(23800,15920) ; U2.10@23912.91,15305.94 23979.06,15305.94 v1(23981,15304) ; v1(24051,14977) 24062.52,14988.52 U2.96@24062.52,15057.91 ; v1(24055,15585) 24062.52,15592.52 U2.30@24062.52,15672.09 ; U2.76@24456.22,15057.91 24456.22,15092.41 v1@24468.46,15104.64
  Bottom Layer w19.68: v1(23981,15175) v1(23981,15304) 24010,15333 24010,15374 24087.79,15451.79 v1(24087.79,15452) ; 24470,14878 24470,14910 ; v1(24486.87,14878) 24486.87,14828.13 24548.56,14766.44 LED1.1@24548.56,14725
  other v1: 24486,14916 24486,14952
VCC12V_SYS: C17.2 C41.1 C50.2 C51.2 D1.2 D2.2 D3.2 D4.1 D7.1 D10.1 D11.1 D13.1 D15.1 D16.2 D17.2 D18.2 D19.1 D20.1 D21.1 D22.1 D24.2 D25.2 DL1.14 DL2.14 DL3.14 Q10.1 R75.2 R104.2 R105.2 R133.1 R266.1 U1.2 | length 19771.2
  Top Layer w31.5: 23351.2,13238 v1(23351.2,13261.83) 23351.2,13579.2 23395.57,13623.57 23853.62,13623.57 v1(23912.38,13682.33) 23963.99,13733.94 v1(23963.99,13953.28)
  Top Layer w60: v1(19767.62,13570) 19876.94,13570 D11.1@19976.94,13470 ; 19923.56,13936.84 v1(20095,13936.84) ; D19.1@20174.55,17145.13 20174.55,17323.1 v1(20176.45,17325) ; v1(20518,17436.78) 20604.22,17523 D4.1@21008,17523 ; D10.1@20812.8,13996 20799.56,14009.24 20799.56,14072.04 20908.52,14181 21122.56,14181 D7.1@21128.56,14175
  Top Layer w78.74: R105.2@20372.6,12168.37 20444.66,12240.43 DL2.14@20579.29,12240.43 20841.38,11978.35 21407.48,11978.35 21516.99,12087.86 DL1.14@21516.99,12240.43 ; R104.2@21321.76,12165.37 21396.82,12240.43 DL1.14@21516.99,12240.43 ; R75.2@22252.76,12167.37 22325.46,12240.08 DL3.14@22459.76,12240.08 ; v1(22792.07,13234.03) v1(22792.07,13194.66) 22953.07,13194.66 ; v1(22997,13234.03) v1(22997,13194.66) ; 23351.2,13238 23307.86,13194.66 v1(23199.75,13194.66) v1(22997,13194.66) ; DL1.14@21516.99,12240.43 21779.08,11978.35 22381.89,11978.35 22459.76,12056.22 DL3.14@22459.76,12240.08 ; DL3.14@22459.76,12240.08 22607.29,12240.08 22997,12629.79 v1(22997,13194.66)
  Bottom Layer w19.68: Q10.1@23860.06,13682.33 v1(23912.38,13682.33) ; R133.1@23963.99,13906.74 v1(23963.99,13953.28)
  Bottom Layer w20: R266.1@21608.39,16917.48 21613.76,16912.11 C50.2@21673.08,16912.11 ; C41.1@21664.39,16570.78 C41.1@21681.39,16587.78 ; C17.2@21679.39,16973.11 U1.2@21679.39,17086.11 ; C50.2@21680.39,16913.11 C17.2@21680.39,16973.11
  Bottom Layer w39.37: v1(22792.07,13194.66) v1(22792.07,13234.03) D16.2@22792.07,13319.06 ; v1(22997,13194.66) v1(22997,13234.03) D17.2@22997,13319.06 ; v1(23199.75,13194.66) v1(23199.75,13234.03) D18.2@23199.75,13319.06 ; v1(23351.2,13209.06) v1(23351.2,13261.83)
  Bottom Layer w40: D21.1@20325.56,16231 20400.24,16305.67 20400.24,16629.24 20448,16677 20752,16677 20771,16696 20771,16756
  Bottom Layer w60: 19315,14005 19785.84,14005 v1(19854,13936.84) ; 20179,13936.23 20491.32,13936.23 20526.13,13971.04 D24.2@20526.13,14030 20758.56,14030 20758.56,14031.21 20871,14143.65 20966.65,14143.65 20993.13,14170.13 D25.2@20993.13,14264.56 ; 20918,16764 21252,16764 21445.22,16570.78 C41.1@21664.39,16570.78
  Bottom Layer w196.85: DL2.14@20579.29,12240.43 20387.78,12048.92 19867.38,12048.92 19269,12647.3 19269,16829 19550,17110 19765,17110 20025,17370 20176.45,17370 20685,17370 20830,17225 20830,17156.61 20830,17140
  other v1: 19767,13616 20144,13937 19902,13938.34 20798.59,14073 20833.15,14107.28 20905.66,16800.89 20946.62,16802 19532.85,17119.44 19580,17120.5 20919.54,17154 20865.66,17156.61 20176.03,17373 20521,17391
X1_MCU: C29.1 U2.35 Y1.1 | length 463
  Bottom Layer w7.87: Y1.1@24005,16070.2 24005,15995.47 C29.1@24005.47,15995 24005.47,15914.8 24072.93,15847.34 24073.41,15847.34 24130.43,15790.32 24130.43,15738.1 24160.94,15707.59 U2.35@24160.94,15672.09
X2_MCU: C28.1 U2.34 Y1.3 | length 588.1
  Bottom Layer w7.87: Y1.3@23918.39,16145 23925,16145 23961.69,16108.31 23961.69,16036.69 23939.06,16014.06 C28.1@23939.06,15995 23939.06,15958.94 24066.41,15831.59 24066.89,15831.59 24114.69,15783.79 24114.69,15731.57 24141.26,15705 U2.34@24141.26,15672.09
按键1: Q28.C R180.2 | length 88.6
  Bottom Layer w7.87: R180.2@23067,14608.27 23116.9,14608.27 Q28.C@23144.26,14580.91
按键1_MCU: R172.1 R174.2 U2.6 | length 928.1
  Bottom Layer w7.87: R172.1@23370.61,14619 23370.71,14619.09 R174.2@23441,14619.09 23547,14725.09 23547,14953.69 23820.52,15227.2 U2.6@23912.91,15227.2
按键2: Q29.C R181.2 | length 88.8
  Bottom Layer w7.87: R181.2@23067,14809 23116.36,14809 Q29.C@23144.26,14781.1
按键2_MCU: R173.1 R175.2 U2.7 | length 759.3
  Bottom Layer w7.87: R173.1@23370.61,14819 23439.5,14819 R175.2@23440,14818.5 23509.21,14887.72 23509.21,14954.89 23801.21,15246.89 U2.7@23912.91,15246.89
按键3: Q31.C R182.2 | length 88
  Bottom Layer w7.87: R182.2@23067,15007.16 23114.8,15007.16 Q31.C@23143.26,14978.7
按键3_MCU: R177.1 R179.2 U2.8 | length 646.1
  Bottom Layer w7.87: R177.1@23370.61,15016 23439.9,15016 R179.2@23440,15016.1 23476.17,15016.1 23726.65,15266.57 U2.8@23912.91,15266.57
按键4: Q30.C R187.2 | length 89.9
  Bottom Layer w7.87: R187.2@23066,15206.57 23105.95,15206.57 Q30.C@23141.26,15171.26
按键4_MCU: R176.1 R178.2 U2.9 | length 584.4
  Bottom Layer w7.87: R176.1@23371.61,15208 R178.2@23440,15208 23452.87,15195.13 23632.93,15195.13 23724.06,15286.26 U2.9@23912.91,15286.26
